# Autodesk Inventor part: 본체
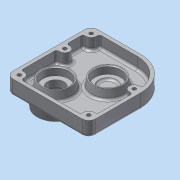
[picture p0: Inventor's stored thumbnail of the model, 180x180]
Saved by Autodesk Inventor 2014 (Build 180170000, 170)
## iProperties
Created: 2015-11
Part Number: 본체
Material: 알루미늄 6061
Document SubType Name: Modeling
Designer: dgall
Density: 2.71 g/cm^3
Appearance: 알루미늄 - 평지
Mass: 247.553 g
Surface Area: 389.424 cm^2
Volume: 91.3479 cm^3
Author: dgall
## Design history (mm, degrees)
sketch "스케치1"
  geometry: L1 (-50, 51.5)-(50, 51.5); L2 (50, 51.5)-(50, -51.5); L3 (50, -51.5)-(-50, -51.5); L4 (-50, -51.5)-(-50, 51.5); 3 further points
  constraints: 8 end point, 2 midpoint, 2 parallel, 1 horizontal, 1 horizontal alignment, 1 perpendicular, 1 vertical alignment
  dimensions: "d0" = 100 distance of L1.start L1.end; "d1" = 103 distance of L3.end L1.start
extrude "돌출1" new body sketch "스케치1" distance "d2" = 18; taper "d3" = 0 deg
fillet "모깎기1" dims "d4" = 40
fillet "모깎기2" dims "d5" = 8
feature "쉘1" dims "d6" = 4
sketch "스케치2"
  geometry: C1 r 6 at (-42, 43.5); C2 r 6 at (-42, -43.5); C3 r 6 at (42, -43.5); C4 r 6 at (-42, 11.5); C5 r 6 at (42, 11.5); A1 r 4 centre (-42, 43.5) between (-42, 47.5) and (-46, 43.5) reference; A2 r 4 centre (42, -43.5) between (42, -47.5) and (46, -43.5) reference; A3 r 8 centre (-42, 43.5) between (-42, 51.5) and (-50, 43.5) reference; A4 r 8 centre (-42, -43.5) between (-50, -43.5) and (-42, -51.5) reference; A5 r 8 centre (42, -43.5) between (42, -51.5) and (50, -43.5) reference; 2 further points
  constraints: 5 centre point, 4 equal radius, 3 coincident, 2 horizontal alignment, 2 vertical alignment
  dimensions: "d7" = 12 diameter of C1
extrude "돌출2" join sketch "스케치2" stored distance "d8" = 18; taper "d9" = 0 deg
fillet "모깎기3" dims "d10" = 3
sketch "스케치3"
  geometry: L1 (-16.944, 91)-(-16.944, 4) reference; L2 (-8.944, -4)-(75.056, -4) reference; C1 r 20 at (43.056, 59); C2 r 20 at (13.056, 26); A1 r 36 centre (43.056, 59) between (77.692, 68.814) and (43.056, 95) reference; 1 further point
  constraints: 2 centre point, 1 coincident, 1 equal radius
  dimensions: "d11" = 30 distance from line of C2.centre L1; "d12" = 30 distance from line of L2 C2.centre; "d13" = 40 diameter of C2
extrude "돌출3" join sketch "스케치3" distance "d14" = 11; taper "d15" = -10 deg
sketch "스케치4"
  geometry: C1 r 20 at (20, -21.5) reference; C2 r 25 at (20, -21.5); 1 further point
  constraints: 1 centre point, 1 coincident
  dimensions: "d16" = 50 diameter of C2
extrude "돌출4" join sketch "스케치4" distance "d17" = 15; taper "d18" = -10 deg
node "작업 평면1"
sketch "스케치5"
  geometry: C1 r 20 at (0, 0) reference; C2 r 16 at (0, 0); C3 r 11 at (0, 0); 1 further point
  constraints: 2 centre point, 2 coincident
  dimensions: "d20" = 32 diameter of C2; "d21" = 22 diameter of C3
extrude "돌출5" cut sketch "스케치5" distance "d22" = 9; taper "d23" = 0 deg
extrude "돌출6" cut sketch "스케치5" distance "d24" = 2; taper "d25" = 0 deg
node "작업 평면2"
sketch "스케치6"
  geometry: L1 (-15, -0.355)-(-15, 44.355) reference; L2 (15, 40.06)-(15, 3.94) reference; L3 (-15, 22)-(15, 22); L4 (-15, 36)-(-4, 36); L5 (-4, 36)-(-4, 34); L6 (-4, 34)-(-2, 34); L7 (-2, 34)-(-2, 32); L8 (-2, 32)-(6, 32); L9 (6, 32)-(6, 38); L10 (6, 38)-(15, 38); 1 further point
  constraints: 16 end point, 5 parallel, 2 midpoint, 2 perpendicular, 2 point on line
  dimensions: "d28" = 28 diameter of L4 L3; "d29" = 24 diameter of L6 L3; "d30" = 20 diameter of L8 L3; "d31" = 32 diameter of L10 L3; "d32" = 11 distance of L4.start L4.end; "d33" = 9 distance of L9.end L10.end; "d34" = 2 distance of L5.end L6.end
revolve "회전1" sketch "스케치6" stored, may be unused: angle "d35" = 90 deg
sketch "스케치7"
  geometry: C1 r 14 at (0, 0) reference; 2 further points
  constraints: 1 vertical alignment
  dimensions: "d36" = 18 distance of C1.centre point (0, 18)
hole "구멍1" sketch "스케치7" at (0, 18) diameter "d37" = 2.459; stored, may be unused: countersink angle "d41" = 90 deg, drill point angle "d43" = 118 deg; dims "d38" = 8, "d39" = 4, "d40" = 2, "d42" = 10
sketch "스케치8"
  geometry: L1 (50, 43.5)-(50, -43.5) reference; L2 (42, -51.5)-(-42, -51.5) reference; L3 (-50, -43.5)-(-50, 11.5) reference; L4 (-10, 51.5)-(42, 51.5) reference; L5 (-46, 2.556)-(-46, -34.556) reference; L6 (-33.056, -47.5)-(33.056, -47.5) reference; L7 (46, -34.556)-(46, 2.556) reference; L8 (46, 20.444)-(46, 34.556) reference; L9 (33.056, 47.5)-(-10, 47.5) reference; A1 r 8 centre (42, 43.5) between (50, 43.5) and (42, 51.5) reference; A2 r 8 centre (-42, -43.5) between (-50, -43.5) and (-42, -51.5) reference; A3 r 8 centre (42, -43.5) between (42, -51.5) and (50, -43.5) reference; A4 r 8 centre (42, 43.5) between (50, 43.5) and (42, 51.5) reference; A5 r 8 centre (42, -43.5) between (42, -51.5) and (50, -43.5) reference; A6 r 8 centre (-42, -43.5) between (-50, -43.5) and (-42, -51.5) reference; A7 r 40 centre (-10, 11.5) between (-10, 51.5) and (-50, 11.5) reference; A8 r 3 centre (-43, -34.556) between (-46, -34.556) and (-42.667, -37.537) reference; A9 r 6 centre (-42, -43.5) between (-36.037, -44.167) and (-42.667, -37.537) reference; A10 r 3 centre (-33.056, -44.5) between (-36.037, -44.167) and (-33.056, -47.5) reference; A11 r 3 centre (33.056, -44.5) between (33.056, -47.5) and (36.037, -44.167) reference; A12 r 6 centre (42, -43.5) between (42.667, -37.537) and (36.037, -44.167) reference; A13 r 3 centre (43, -34.556) between (42.667, -37.537) and (46, -34.556) reference; A14 r 3 centre (43, 2.556) between (46, 2.556) and (42.667, 5.537) reference; A15 r 6 centre (42, 11.5) between (42.667, 17.463) and (42.667, 5.537) reference; A16 r 3 centre (43, 20.444) between (42.667, 17.463) and (46, 20.444) reference; A17 r 3 centre (43, 34.556) between (46, 34.556) and (42.667, 37.537) reference; A18 r 6 centre (42, 43.5) between (36.037, 44.167) and (42.667, 37.537) reference; A19 r 3 centre (33.056, 44.5) between (36.037, 44.167) and (33.056, 47.5) reference; A20 r 36 centre (-10, 11.5) between (-10, 47.5) and (-44.636, 21.314) reference; A21 r 3 centre (-41.75, 20.497) between (-44.636, 21.314) and (-41.833, 17.498) reference; A22 r 6 centre (-42, 11.5) between (-42.667, 5.537) and (-41.833, 17.498) reference; A23 r 3 centre (-43, 2.556) between (-42.667, 5.537) and (-46, 2.556) reference; 1 further point
hole "구멍2" sketch "스케치8" at (-42, 11.5), (-42, -43.5), (42, -43.5), (42, 11.5), (42, 43.5) diameter "d47" = 4.5; stored, may be unused: countersink angle "d51" = 90 deg, drill point angle "d53" = 118 deg; dims "d48" = 8, "d49" = 8, "d50" = 4.4, "d52" = 10
fillet "모깎기4" dims "d54" = 0.3
fillet "모깎기5" dims "d55" = 3
chamfer "모따기1" distance "d56" = 1; stored, may be unused: second distance "d57" = 2, angle "d58" = 45 deg
sketch "스케치9"
  geometry: L1 (-14.887, 35.102)-(34.887, 35.102); L2 (34.887, 35.102)-(34.887, 27.898); L3 (34.887, 27.898)-(-14.887, 27.898); L4 (-14.887, 27.898)-(-14.887, 35.102); L5 (50, -16.189)-(50, 43.5) reference; L6 (42, 51.5)-(-10, 51.5) reference; 4 further points
  constraints: 2 midpoint, 1 horizontal alignment, 1 vertical alignment, 2 other
  dimensions: "d59" = 40 distance from line of L5 point (10, 31.5); "d60" = 20 distance from line of L6 point (10, 31.5)
feature "엠보싱1" sketch "스케치9" dims "d0" = 100, "d1" = 103, "d61" = 0.5, "d62" = 0
node "솔리드1"
pattern_circular "원형 패턴1" dims angle "d45" = 360 deg
node "투영된 루프1"
other parameters: "d19" = -9
